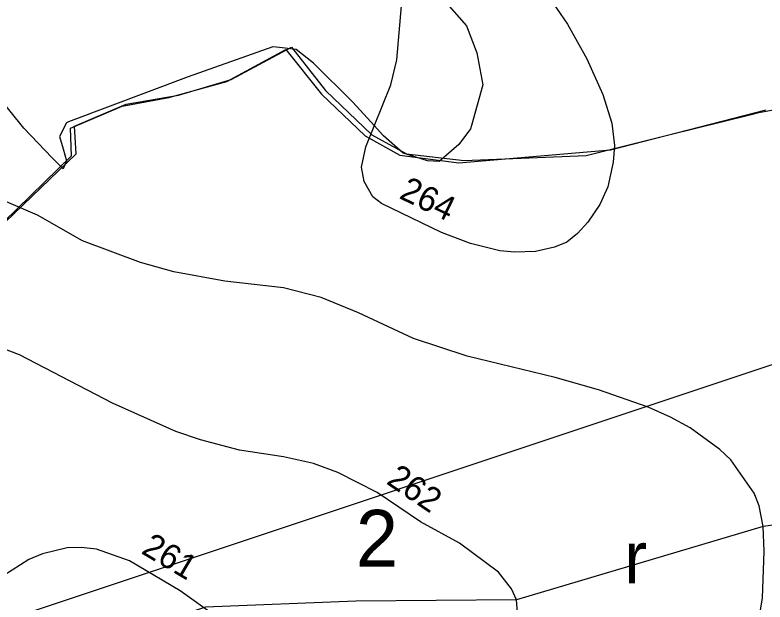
# Model space of a CAD drawing. Extents: x -662500 to -653478, y -1056827 to -1049993.
# Drawn here: x -661076.7 to -660772.3, y -1051447.1 to -1051208.8 of the extents above; entities that cross this region are included whole.
import ezdxf

# ---------------------------------------------------------------- set-up
doc = ezdxf.new("R2010")
doc.units = 0
for name, color, linetype in [('58', 7, 'Continuous'), ('Vrstva 1', 7, 'Continuous'), ('Vrstva 24', 7, 'Continuous'), ('Vrstva 47', 7, 'Continuous'), ('Vrstva 5', 7, 'Continuous'), ('Vrstva 57', 7, 'Continuous'), ('Vrstva 7', 7, 'Continuous')]:
    doc.layers.add(name, color=color, linetype=linetype)

msp = doc.modelspace()

# ---------------------------------------------------------------- linework, layer by layer
at = {"layer": '58'}
msp.add_lwpolyline([(-661249.95, -1051465.32), (-661202.87, -1051401.23), (-661170.76, -1051367.99), (-661128.4, -1051334.38), (-661098.4, -1051308.72), (-661088.02, -1051299.84), (-661051.96, -1051265.12), (-661052.56, -1051253.85), (-661031.67, -1051244.99), (-661010.4, -1051241.29), (-660989, -1051234.91), (-660964.43, -1051221.82), (-660950.74, -1051239.44), (-660931.94, -1051257.44), (-660917.85, -1051265.11), (-660894.35, -1051267.88), (-660844.89, -1051265.84), (-660810.8, -1051257.33), (-660778.45, -1051249.25), (-660774.82, -1051248.34), (-660759.57, -1051245.48)], dxfattribs=at)
at = {"layer": 'Vrstva 1'}
msp.add_lwpolyline([(-661250.88, -1051466.71), (-661204.06, -1051402.7), (-661171.31, -1051368.85), (-661098.04, -1051309.04), (-661053.75, -1051265.91), (-661054.19, -1051254.74), (-661033.26, -1051245.73), (-661014.35, -1051242.25), (-660990.78, -1051235.74), (-660966.73, -1051222.77), (-660952.3, -1051240.94), (-660934.53, -1051257.84), (-660920.58, -1051265.72), (-660896.52, -1051268.79), (-660834.98, -1051263.49), (-660771.93, -1051247.32)], dxfattribs=at)
at = {"layer": 'Vrstva 24'}
msp.add_lwpolyline([(-660901.39, -1051204.06), (-660893.41, -1051213.15), (-660889.28, -1051224.16), (-660886.8, -1051237.1), (-660891.49, -1051253.59), (-660891.89, -1051255), (-660896.58, -1051261.33), (-660904.56, -1051268.22), (-660909.24, -1051267.94), (-660919.15, -1051264.91), (-660927.14, -1051257.75), (-660932.13, -1051252.32), (-660939.8, -1051243.98), (-660955.5, -1051228.29), (-660962.66, -1051222.78), (-660969.36, -1051221.99), (-660972.02, -1051221.68), (-661006.44, -1051233.8), (-661054.97, -1051252.18), (-661055.86, -1051252.52), (-661058.62, -1051258.03), (-661057.21, -1051263.08), (-661055.86, -1051267.94), (-661057.24, -1051271.24), (-661061.63, -1051266.7), (-661073.21, -1051254.72), (-661093.86, -1051229.12)], dxfattribs=at)
at = {"layer": 'Vrstva 47'}
msp.add_line((-659893.49, -1051058.49), (-661206.18, -1051496.55), dxfattribs=at)
at = {"layer": 'Vrstva 5'}
msp.add_lwpolyline([(-661250.88, -1051466.71), (-661202.87, -1051401.23), (-661171.31, -1051368.85), (-661098.04, -1051309.04), (-661053.75, -1051265.91), (-661054.19, -1051254.74), (-661031.67, -1051244.99), (-661010.4, -1051241.29), (-660989, -1051234.91), (-660966.73, -1051222.77), (-660952.3, -1051240.94), (-660934.53, -1051257.84), (-660920.58, -1051265.72), (-660896.52, -1051268.79), (-660834.98, -1051263.49), (-660771.93, -1051247.32)], dxfattribs=at)
at = {"layer": 'Vrstva 57'}
msp.add_lwpolyline([(-660701.47, -1051406.86), (-660773.01, -1051416.51), (-660873.2, -1051446.27), (-660938.34, -1051446.81), (-660938.34, -1051446.81), (-660999.43, -1051449.16), (-661037.5, -1051461.84), (-661150.11, -1051538.24)], dxfattribs=at)
at = {"layer": 'Vrstva 7'}
for p, q in [((-660860.45, -1051200.81), (-660852.51, -1051212.44)), ((-660921.67, -1051226.89), (-660919.83, -1051205.06)), ((-660852.51, -1051212.44), (-660844.57, -1051226.61)), ((-660924.22, -1051237.09), (-660921.67, -1051226.89)), ((-660844.57, -1051226.61), (-660838.06, -1051241.06)), ((-660934.28, -1051262.32), (-660924.22, -1051237.09)), ((-660838.06, -1051241.06), (-660834.51, -1051252.68)), ((-660834.51, -1051252.68), (-660833.38, -1051261.75)), ((-660936.12, -1051270.54), (-660934.28, -1051262.32)), ((-660833.38, -1051261.75), (-660833.95, -1051268.55)), ((-660833.95, -1051268.55), (-660836.07, -1051278.48)), ((-660934.99, -1051276.35), (-660936.12, -1051270.54)), ((-660931.45, -1051282.58), (-660934.99, -1051276.35)), ((-660836.07, -1051278.48), (-660839.33, -1051285.7)), ((-661067.64, -1051290.09), (-661080.25, -1051284.57)), ((-660927.9, -1051285.28), (-660931.45, -1051282.58)), ((-660903.67, -1051297.04), (-660927.9, -1051285.28)), ((-660839.33, -1051285.7), (-660844.15, -1051292.93)), ((-661049.35, -1051300.44), (-661067.64, -1051290.09)), ((-660844.15, -1051292.93), (-660848.4, -1051297.46)), ((-660891.77, -1051301.57), (-660903.67, -1051297.04)), ((-660848.4, -1051297.46), (-660852.79, -1051301.01)), ((-661025.83, -1051309.23), (-661049.35, -1051300.44)), ((-660879.86, -1051304.55), (-660891.77, -1051301.57)), ((-660857.75, -1051302.99), (-660865.41, -1051304.83)), ((-660852.79, -1051301.01), (-660857.75, -1051302.99)), ((-660873.91, -1051305.12), (-660879.86, -1051304.55)), ((-660865.41, -1051304.83), (-660873.91, -1051305.12)), ((-661012.22, -1051313.05), (-661025.83, -1051309.23)), ((-660991.54, -1051316.88), (-661012.22, -1051313.05)), ((-660967.73, -1051319.57), (-660991.54, -1051316.88)), ((-660952.42, -1051323.4), (-660967.73, -1051319.57)), ((-660937.26, -1051329.63), (-660952.42, -1051323.4)), ((-660915.01, -1051340.12), (-660937.26, -1051329.63)), ((-661074.86, -1051346.78), (-661086.77, -1051342.25)), ((-660893.18, -1051347.35), (-660915.01, -1051340.12)), ((-661037.17, -1051366.34), (-661074.86, -1051346.78)), ((-660857.47, -1051355.99), (-660893.18, -1051347.35)), ((-660839.9, -1051360.95), (-660857.47, -1051355.99)), ((-660819.77, -1051368.04), (-660839.9, -1051360.95)), ((-661011.38, -1051377.82), (-661037.17, -1051366.34)), ((-660810.7, -1051372.01), (-660819.77, -1051368.04)), ((-660802.63, -1051376.4), (-660810.7, -1051372.01)), ((-661001.45, -1051381.22), (-661011.38, -1051377.82)), ((-660790.58, -1051385.19), (-660802.63, -1051376.4)), ((-660985.58, -1051385.47), (-661001.45, -1051381.22)), ((-660786.19, -1051389.44), (-660790.58, -1051385.19)), ((-660967.73, -1051388.16), (-660985.58, -1051385.47)), ((-660955.54, -1051390.86), (-660967.73, -1051388.16)), ((-660945.62, -1051394.54), (-660955.54, -1051390.86)), ((-660776.69, -1051402.9), (-660786.19, -1051389.44)), ((-660929.75, -1051402.62), (-660945.62, -1051394.54)), ((-660912.17, -1051414.52), (-660929.75, -1051402.62)), ((-660774.71, -1051408), (-660776.69, -1051402.9)), ((-660773.01, -1051416.51), (-660774.71, -1051408)), ((-660896.3, -1051423.17), (-660912.17, -1051414.52)), ((-660772.58, -1051426.43), (-660773.01, -1051416.51)), ((-660880.43, -1051434.93), (-660896.3, -1051423.17)), ((-661065.51, -1051427.56), (-661071.18, -1051429.83)), ((-661055.59, -1051425.15), (-661065.51, -1051427.56)), ((-661049.92, -1051425.01), (-661055.59, -1051425.15)), ((-661043.69, -1051425.72), (-661049.92, -1051425.01)), ((-661030.22, -1051430.4), (-661043.69, -1051425.72)), ((-660773.29, -1051445.56), (-660772.58, -1051426.43)), ((-661071.18, -1051429.83), (-661081.24, -1051436.35)), ((-661009.67, -1051442.58), (-661030.22, -1051430.4)), ((-660875.19, -1051441.73), (-660880.43, -1051434.93)), ((-660994.94, -1051453.07), (-661009.67, -1051442.58)), ((-660873.2, -1051446.27), (-660875.19, -1051441.73)), ((-660775.98, -1051461.57), (-660773.29, -1051445.56)), ((-660872.63, -1051453.07), (-660873.2, -1051446.27))]:
    msp.add_line(p, q, dxfattribs=at)

# ---------------------------------------------------------------- texts
at = {"layer": 'Vrstva 5'}
msp.add_text('r', height=21, dxfattribs=at).set_placement((-660829.44, -1051439.48))
at = {"layer": 'Vrstva 57'}
msp.add_text('2', height=23, dxfattribs=at).set_placement((-660938.34, -1051432.71))
at = {"layer": 'Vrstva 7'}
for s, rotation, p in [('264', 334.1103, (-660921.2, -1051282.97)), ('262', 325.8862, (-660926.44, -1051398.81)), ('261', 329.3291, (-661025.92, -1051427.13))]:
    msp.add_text(s, height=10, rotation=rotation, dxfattribs=at).set_placement(p)

doc.saveas('drawing.dxf')
